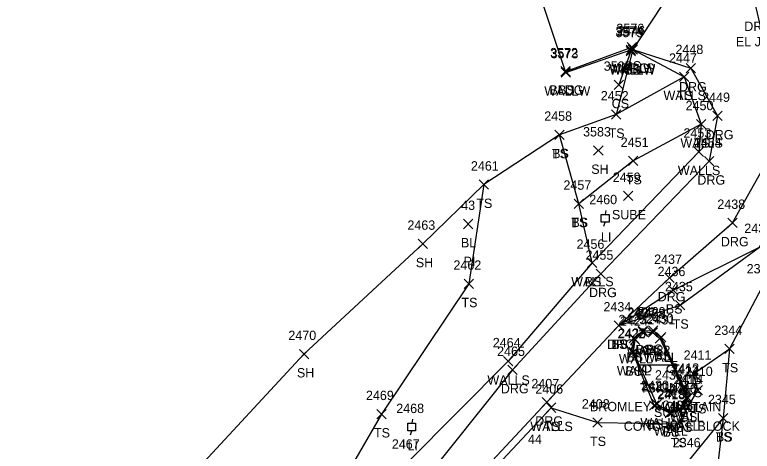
# Model space of a CAD drawing. Extents: x 49137 to 50946, y 9590 to 10709.
# Drawn here: x 49768.6 to 49926.3, y 10093.2 to 10186.5 of the extents above; entities that cross this region are included whole.
import ezdxf

# ---------------------------------------------------------------- set-up
doc = ezdxf.new("R2010")
doc.units = 0
for name, color, linetype in [('C_A', 7, 'Continuous'), ('C_C', 7, 'Continuous'), ('C_I', 7, 'Continuous'), ('C_TIC', 7, 'Continuous'), ('L_A', 7, 'Continuous'), ('L_C', 7, 'Continuous'), ('L_I', 7, 'Continuous'), ('L_TIC', 7, 'Continuous'), ('LBC', 7, 'Continuous'), ('LELB', 7, 'Continuous'), ('LSOGP', 7, 'Continuous'), ('LW', 7, 'Continuous'), ('LWS', 7, 'Continuous'), ('R_A', 7, 'Continuous'), ('R_I', 7, 'Continuous'), ('R_TIC', 7, 'Continuous'), ('RDG', 7, 'Continuous'), ('S_A', 7, 'Continuous'), ('S_C', 7, 'Continuous'), ('S_I', 7, 'Continuous'), ('SSGN', 7, 'Continuous'), ('U_A', 7, 'Continuous'), ('U_C', 7, 'Continuous'), ('U_I', 7, 'Continuous'), ('U_TIC', 7, 'Continuous'), ('ULP', 7, 'Continuous')]:
    doc.layers.add(name, color=color, linetype=linetype)

msp = doc.modelspace()

# ---------------------------------------------------------------- linework, layer by layer
at = {"layer": 'C_TIC'}
for points in [[(49864.54, 10140.8), (49866.54, 10142.8)], [(49866.54, 10140.8), (49864.54, 10142.8)]]:
    msp.add_lwpolyline(points, dxfattribs=at)
at = {"layer": 'L_TIC'}
for points in [[(49899.33, 10178.03), (49901.33, 10180.03)], [(49901.33, 10178.03), (49899.33, 10180.03)], [(49899.56, 10178.6), (49901.56, 10180.6)], [(49901.56, 10178.6), (49899.56, 10180.6)], [(49899.79, 10178.12), (49901.79, 10180.12)], [(49901.79, 10178.12), (49899.79, 10180.12)], [(49899.35, 10177.73), (49901.35, 10179.73)], [(49901.35, 10177.73), (49899.35, 10179.73)], [(49899.35, 10177.73), (49901.35, 10179.73)], [(49901.35, 10177.73), (49899.35, 10179.73)], [(49885.35, 10173.43), (49887.35, 10175.43)], [(49887.35, 10173.43), (49885.35, 10175.43)], [(49885.35, 10173.43), (49887.35, 10175.43)], [(49887.35, 10173.43), (49885.35, 10175.43)], [(49885.44, 10173.21), (49887.44, 10175.21)], [(49887.44, 10173.21), (49885.44, 10175.21)], [(49910.78, 10172.27), (49912.78, 10174.27)], [(49912.78, 10172.27), (49910.78, 10174.27)], [(49910.78, 10172.27), (49912.78, 10174.27)], [(49912.78, 10172.27), (49910.78, 10174.27)], [(49896.81, 10170.55), (49898.81, 10172.55)], [(49898.81, 10170.55), (49896.81, 10172.55)], [(49896.19, 10164.22), (49898.19, 10166.22)], [(49898.19, 10164.22), (49896.19, 10166.22)], [(49914.41, 10162.12), (49916.41, 10164.12)], [(49916.41, 10162.12), (49914.41, 10164.12)], [(49914.41, 10162.12), (49916.41, 10164.12)], [(49916.41, 10162.12), (49914.41, 10164.12)], [(49884.09, 10159.86), (49886.09, 10161.86)], [(49886.09, 10159.86), (49884.09, 10161.86)], [(49884.09, 10159.86), (49886.09, 10161.86)], [(49886.09, 10159.86), (49884.09, 10161.86)], [(49892.4, 10156.51), (49894.4, 10158.51)], [(49894.4, 10156.51), (49892.4, 10158.51)], [(49913.87, 10156.25), (49915.87, 10158.25)], [(49915.87, 10156.25), (49913.87, 10158.25)], [(49899.88, 10154.28), (49901.88, 10156.28)], [(49901.88, 10154.28), (49899.88, 10156.28)], [(49867.9, 10149.22), (49869.9, 10151.22)], [(49869.9, 10149.22), (49867.9, 10151.22)], [(49888.2, 10145.12), (49890.2, 10147.12)], [(49890.2, 10145.12), (49888.2, 10147.12)], [(49888.2, 10145.12), (49890.2, 10147.12)], [(49890.2, 10145.12), (49888.2, 10147.12)], [(49854.88, 10136.56), (49856.88, 10138.56)], [(49856.88, 10136.56), (49854.88, 10138.56)], [(49891.06, 10132.5), (49893.06, 10134.5)], [(49893.06, 10132.5), (49891.06, 10134.5)], [(49891.06, 10132.5), (49893.06, 10134.5)], [(49893.06, 10132.5), (49891.06, 10134.5)], [(49864.73, 10128.02), (49866.73, 10130.02)], [(49866.73, 10128.02), (49864.73, 10130.02)], [(49908.39, 10126.66), (49910.39, 10128.66)], [(49910.39, 10126.66), (49908.39, 10128.66)], [(49909.91, 10123.43), (49911.91, 10125.43)], [(49911.91, 10123.43), (49909.91, 10125.43)], [(49896.76, 10119.11), (49898.76, 10121.11)], [(49898.76, 10119.11), (49896.76, 10121.11)], [(49896.76, 10119.11), (49898.76, 10121.11)], [(49898.76, 10119.11), (49896.76, 10121.11)], [(49901.89, 10117.97), (49903.89, 10119.97)], [(49903.89, 10117.97), (49901.89, 10119.97)], [(49904.11, 10118.04), (49906.11, 10120.04)], [(49906.11, 10118.04), (49904.11, 10120.04)], [(49899.96, 10116.37), (49901.96, 10118.37)], [(49901.96, 10116.37), (49899.96, 10118.37)], [(49901.93, 10117.77), (49903.93, 10119.77)], [(49903.93, 10117.77), (49901.93, 10119.77)], [(49904.03, 10117.63), (49906.03, 10119.63)], [(49906.03, 10117.63), (49904.03, 10119.63)], [(49905.86, 10116.6), (49907.86, 10118.6)], [(49907.86, 10116.6), (49905.86, 10118.6)], [(49905.86, 10116.6), (49907.86, 10118.6)], [(49907.86, 10116.6), (49905.86, 10118.6)], [(49900.3, 10116.04), (49902.3, 10118.04)], [(49902.3, 10116.04), (49900.3, 10118.04)], [(49905.59, 10116.33), (49907.59, 10118.33)], [(49907.59, 10116.33), (49905.59, 10118.33)], [(49905.59, 10116.33), (49907.59, 10118.33)], [(49907.59, 10116.33), (49905.59, 10118.33)], [(49899.76, 10113.35), (49901.76, 10115.35)], [(49901.76, 10113.35), (49899.76, 10115.35)], [(49899.89, 10113.47), (49901.89, 10115.47)], [(49901.89, 10113.47), (49899.89, 10115.47)], [(49920.48, 10114.09), (49922.48, 10116.09)], [(49922.48, 10114.09), (49920.48, 10116.09)], [(49829.47, 10113), (49831.47, 10115)], [(49831.47, 10113), (49829.47, 10115)], [(49873.14, 10111.45), (49875.14, 10113.45)], [(49875.14, 10111.45), (49873.14, 10113.45)], [(49912.76, 10108.78), (49914.76, 10110.78)], [(49914.76, 10108.78), (49912.76, 10110.78)], [(49910.61, 10105.6), (49912.61, 10107.6)], [(49912.61, 10105.6), (49910.61, 10107.6)], [(49910.61, 10105.6), (49912.61, 10107.6)], [(49912.61, 10105.6), (49910.61, 10107.6)], [(49910.72, 10106.01), (49912.72, 10108.01)], [(49912.72, 10106.01), (49910.72, 10108.01)], [(49910.72, 10106.01), (49912.72, 10108.01)], [(49912.72, 10106.01), (49910.72, 10108.01)], [(49913.69, 10105.31), (49915.69, 10107.31)], [(49915.69, 10105.31), (49913.69, 10107.31)], [(49904.9, 10102.32), (49906.9, 10104.32)], [(49906.9, 10102.32), (49904.9, 10104.32)], [(49911.17, 10103.57), (49913.17, 10105.57)], [(49913.17, 10103.57), (49911.17, 10105.57)], [(49911.56, 10103.61), (49913.56, 10105.61)], [(49913.56, 10103.61), (49911.56, 10105.61)], [(49882.33, 10101.54), (49884.33, 10103.54)], [(49884.33, 10101.54), (49882.33, 10103.54)], [(49882.33, 10101.54), (49884.33, 10103.54)], [(49884.33, 10101.54), (49882.33, 10103.54)], [(49904.33, 10102), (49906.33, 10104)], [(49906.33, 10102), (49904.33, 10104)], [(49910.25, 10101.62), (49912.25, 10103.62)], [(49912.25, 10101.62), (49910.25, 10103.62)], [(49910.51, 10101.33), (49912.51, 10103.33)], [(49912.51, 10101.33), (49910.51, 10103.33)], [(49846.02, 10100.17), (49848.02, 10102.17)], [(49848.02, 10100.17), (49846.02, 10102.17)], [(49907.72, 10100.34), (49909.72, 10102.34)], [(49909.72, 10100.34), (49907.72, 10102.34)], [(49907.76, 10100.54), (49909.76, 10102.54)], [(49909.76, 10100.54), (49907.76, 10102.54)], [(49919.1, 10099.3), (49921.1, 10101.3)], [(49921.1, 10099.3), (49919.1, 10101.3)], [(49919.1, 10099.3), (49921.1, 10101.3)], [(49921.1, 10099.3), (49919.1, 10101.3)], [(49892.22, 10098.35), (49894.22, 10100.35)], [(49894.22, 10098.35), (49892.22, 10100.35)], [(49909.47, 10098.06), (49911.47, 10100.06)], [(49911.47, 10098.06), (49909.47, 10100.06)]]:
    msp.add_lwpolyline(points, dxfattribs=at)
at = {"layer": 'LBC'}
msp.add_lwpolyline([(49886.35, 10174.43), (49872.96, 10214.58), (49870.73, 10223.1), (49860.63, 10220.72)], dxfattribs=at)
at = {"layer": 'LELB'}
for points in [[(49955.98, 10224.66), (49962.11, 10206.73), (49963.32, 10197.72), (49964.68, 10176.23), (49967.05, 10162.1), (49944.13, 10145.25), (49928.38, 10128.24), (49921.48, 10115.09), (49920.1, 10100.3), (49918.19, 10083.85), (49918.93, 10078.25)], [(49897.76, 10120.11), (49909.39, 10127.66), (49927.87, 10136.88), (49941.26, 10158.78), (49931.78, 10188.79), (49933.01, 10213.1)], [(49886.35, 10174.43), (49900.56, 10179.6)], [(49900.35, 10178.73), (49897.81, 10171.55)], [(49911.78, 10173.27), (49897.19, 10165.22), (49885.09, 10160.86), (49868.9, 10150.22), (49865.73, 10129.02), (49847.02, 10101.17), (49823, 10059.67)], [(49915.41, 10163.12), (49900.88, 10155.28), (49889.2, 10146.12)], [(49892.06, 10133.5), (49889.2, 10146.12), (49885.09, 10160.86)], [(49897.76, 10120.11), (49910.91, 10124.43), (49927.87, 10136.88)], [(49911.72, 10107.01), (49912.56, 10104.61), (49911.51, 10102.33), (49908.72, 10101.34), (49905.33, 10103), (49900.76, 10114.35), (49900.96, 10117.37), (49902.89, 10118.97), (49905.11, 10119.04), (49906.86, 10117.6)], [(49911.72, 10107.01), (49906.86, 10117.6)], [(49913.76, 10109.78), (49921.48, 10115.09)], [(49883.33, 10102.54), (49893.22, 10099.35), (49910.47, 10099.06), (49914.69, 10106.31), (49913.76, 10109.78)], [(49920.1, 10100.3), (49912.63, 10091.09), (49904.43, 10086.39)]]:
    msp.add_lwpolyline(points, dxfattribs=at)
at = {"layer": 'LSOGP'}
msp.add_lwpolyline([(49921.15, 10210.06), (49900.78, 10179.13), (49897.19, 10165.22), (49885.09, 10160.86), (49868.89, 10150.22), (49855.88, 10137.57), (49830.46, 10114), (49806.41, 10088.03), (49776.2, 10083.52), (49760.59, 10076.2)], dxfattribs=at)
at = {"layer": 'LW'}
for points in [[(49886.44, 10174.21), (49900.33, 10179.03), (49900.35, 10178.73)], [(49911.61, 10106.6), (49912.17, 10104.57), (49911.25, 10102.62), (49908.76, 10101.54), (49905.9, 10103.32), (49900.89, 10114.47), (49901.3, 10117.04), (49902.93, 10118.77), (49905.03, 10118.63), (49906.59, 10117.33)], [(49911.61, 10106.6), (49906.59, 10117.33)]]:
    msp.add_lwpolyline(points, dxfattribs=at)
at = {"layer": 'LWS'}
for points in [[(49900.79, 10179.12), (49911.78, 10173.27), (49915.41, 10163.12), (49914.87, 10157.25), (49892.06, 10133.5), (49874.14, 10112.45), (49852.55, 10090.77), (49823, 10059.67), (49804.33, 10038.47)], [(49828.96, 10027.58), (49828.08, 10031.4), (49832.44, 10045.24), (49853.25, 10070.35), (49883.33, 10102.54)]]:
    msp.add_lwpolyline(points, dxfattribs=at)
at = {"layer": 'R_TIC'}
for points in [[(49899.79, 10178.12), (49901.79, 10180.12)], [(49901.79, 10178.12), (49899.79, 10180.12)], [(49912.16, 10174.13), (49914.16, 10176.13)], [(49914.16, 10174.13), (49912.16, 10176.13)], [(49917.87, 10163.89), (49919.87, 10165.89)], [(49919.87, 10163.89), (49917.87, 10165.89)], [(49916.09, 10154.21), (49918.09, 10156.21)], [(49918.09, 10154.21), (49916.09, 10156.21)], [(49921.11, 10141.03), (49923.11, 10143.03)], [(49923.11, 10141.03), (49921.11, 10143.03)], [(49892.92, 10130.16), (49894.92, 10132.16)], [(49894.92, 10130.16), (49892.92, 10132.16)], [(49907.6, 10129.27), (49909.6, 10131.27)], [(49909.6, 10129.27), (49907.6, 10131.27)], [(49896.76, 10119.11), (49898.76, 10121.11)], [(49898.76, 10119.11), (49896.76, 10121.11)], [(49874.07, 10109.6), (49876.07, 10111.6)], [(49876.07, 10109.6), (49874.07, 10111.6)], [(49881.42, 10102.69), (49883.42, 10104.69)], [(49883.42, 10102.69), (49881.42, 10104.69)]]:
    msp.add_lwpolyline(points, dxfattribs=at)
at = {"layer": 'RDG'}
for points in [[(49797.89, 10003.45), (49806.67, 10020.9), (49821.46, 10037.44), (49832.34, 10049.67), (49852.34, 10071.47), (49882.42, 10103.69), (49897.76, 10120.11), (49908.6, 10130.27), (49922.11, 10142.03), (49933.26, 10161.9), (49927.13, 10188.06), (49921.15, 10210.06)], [(49900.79, 10179.12), (49913.16, 10175.13), (49918.87, 10164.89), (49917.09, 10155.21), (49893.92, 10131.16), (49875.07, 10110.6), (49855.27, 10085.88), (49826.17, 10056.49), (49807.26, 10034.98), (49792.19, 10024.42), (49776.73, 10026.67)]]:
    msp.add_lwpolyline(points, dxfattribs=at)
at = {"layer": 'SSGN'}
for p, q in [((49902.1, 10111.7), (49910.7, 10111.7)), ((49906.13, 10110.8), (49906.13, 10110.8))]:
    msp.add_line(p, q, dxfattribs=at)
for centre in [(49903.76, 10110.87), (49908.98, 10110.8)]:
    msp.add_circle(centre, 0.833, dxfattribs=at)
at = {"layer": 'U_TIC'}
for points in [[(49898.77, 10146.8), (49900.77, 10148.8)], [(49900.77, 10146.8), (49898.77, 10148.8)], [(49907.77, 10104.54), (49909.77, 10106.54)], [(49909.77, 10104.54), (49907.77, 10106.54)]]:
    msp.add_lwpolyline(points, dxfattribs=at)
at = {"layer": 'ULP'}
for p, q in [((49894.03, 10142.19), (49894.03, 10143.86)), ((49894.03, 10143.86), (49895.69, 10143.86)), ((49895.03, 10144.69), (49894.86, 10143.86)), ((49895.69, 10143.86), (49895.69, 10142.19)), ((49895.69, 10142.19), (49894.03, 10142.19)), ((49894.61, 10141.36), (49894.86, 10142.19)), ((49894.86, 10143.03), (49894.86, 10143.03)), ((49853.67, 10100.06), (49853.5, 10099.23)), ((49852.67, 10097.56), (49852.67, 10099.23)), ((49852.67, 10099.23), (49854.33, 10099.23)), ((49853.5, 10098.39), (49853.5, 10098.39)), ((49854.33, 10099.23), (49854.33, 10097.56)), ((49854.33, 10097.56), (49852.67, 10097.56)), ((49853.25, 10096.73), (49853.5, 10097.56))]:
    msp.add_line(p, q, dxfattribs=at)

# ---------------------------------------------------------------- texts
at = {"layer": 'C_A'}
msp.add_text('BL', height=2, dxfattribs=at).set_placement((49864.02, 10136.8))
at = {"layer": 'C_C'}
msp.add_text('PI', height=2, dxfattribs=at).set_placement((49864.59, 10132.8))
at = {"layer": 'C_I'}
for s, p in [('43', (49864.07, 10144.8)), ('44', (49878.35, 10094.8))]:
    msp.add_text(s, height=2, dxfattribs=at).set_placement(p)
at = {"layer": 'L_A'}
for s, p in [('WALLW', (49895.75, 10174.03)), ('WALLW', (49895.76, 10173.73)), ('WALLS', (49896.33, 10174.12)), ('CS', (49898.79, 10173.73)), ('BS', (49899, 10174.6)), ('WALLW', (49881.86, 10169.21)), ('BLDG', (49882.94, 10169.43)), ('BS', (49884.79, 10169.43)), ('WALLS', (49907.33, 10168.27)), ('TS', (49910.19, 10168.27)), ('CS', (49896.25, 10166.55)), ('TS', (49895.6, 10160.22)), ('WALLS', (49910.96, 10158.12)), ('TS', (49913.82, 10158.12)), ('TS', (49883.5, 10155.86)), ('BS', (49883.53, 10155.86)), ('SH', (49891.89, 10152.51)), ('WALLS', (49910.41, 10152.25)), ('TS', (49899.29, 10150.28)), ('TS', (49867.31, 10145.22)), ('TS', (49887.61, 10141.12)), ('BS', (49887.64, 10141.12)), ('SH', (49854.37, 10132.56)), ('WALLS', (49887.6, 10128.5)), ('BS', (49890.5, 10128.5)), ('TS', (49864.13, 10124.02)), ('BS', (49907.83, 10122.66)), ('TS', (49909.31, 10119.43)), ('TS', (49896.17, 10115.11)), ('BS', (49896.2, 10115.11)), ('WALL', (49899.42, 10113.77)), ('WALL', (49901.51, 10113.63)), ('BS', (49901.33, 10113.97)), ('BS', (49903.55, 10114.04)), ('WALL', (49897.79, 10112.04)), ('BS', (49899.4, 10112.37)), ('WALL', (49903.08, 10112.33)), ('WALL', (49903.08, 10112.33)), ('BS', (49905.31, 10112.6)), ('BS', (49905.31, 10112.6)), ('TS', (49919.89, 10110.09)), ('SH', (49828.95, 10109)), ('WALL', (49897.37, 10109.47)), ('BS', (49899.2, 10109.35)), ('WALLS', (49869.68, 10107.45)), ('TS', (49912.17, 10104.78)), ('WALL', (49908.1, 10101.6)), ('WALL', (49908.1, 10101.6)), ('BS', (49910.16, 10102.01)), ('BS', (49910.16, 10102.01)), ('TS', (49913.1, 10101.31)), ('WALL', (49908.66, 10099.57)), ('BS', (49911, 10099.61)), ('WALLS', (49878.87, 10097.54)), ('TS', (49881.74, 10097.54)), ('WALL', (49902.39, 10098.32)), ('BS', (49903.77, 10098)), ('WALL', (49907.74, 10097.62)), ('TS', (49845.43, 10096.17)), ('WALL', (49905.25, 10096.54)), ('BS', (49907.16, 10096.34)), ('BS', (49909.95, 10097.33)), ('TS', (49891.63, 10094.35)), ('TS', (49918.51, 10095.3)), ('BS', (49918.54, 10095.3)), ('TS', (49908.88, 10094.06))]:
    msp.add_text(s, height=2, dxfattribs=at).set_placement(p)
at = {"layer": 'L_C'}
msp.add_text('CONCRETE BLOCK', height=2, dxfattribs=at).set_placement((49898.85, 10097.6))
msp.add_text('CONCRETE BLOCK', height=2, dxfattribs=at).set_placement((49898.85, 10097.6))
at = {"layer": 'L_I'}
for s, p in [('3576', (49897.25, 10182.6)), ('3574', (49897.07, 10182.03)), ('3575', (49897.09, 10181.73)), ('3575', (49897.09, 10181.73)), ('2446', (49897.47, 10182.12)), ('3572', (49883.09, 10177.43)), ('3572', (49883.09, 10177.43)), ('3573', (49883.18, 10177.21)), ('2447', (49908.52, 10176.27)), ('2447', (49908.52, 10176.27)), ('3582', (49894.55, 10174.55)), ('2452', (49893.93, 10168.22)), ('2450', (49912.07, 10166.12)), ('2450', (49912.07, 10166.12)), ('2458', (49881.83, 10163.86)), ('2458', (49881.83, 10163.86)), ('3583', (49890.14, 10160.51)), ('2453', (49911.61, 10160.25)), ('2451', (49898.19, 10158.28)), ('2461', (49866.16, 10153.22)), ('2457', (49885.94, 10149.12)), ('2457', (49885.94, 10149.12)), ('2463', (49852.57, 10140.56)), ('2439', (49924.61, 10139.88)), ('2439', (49924.61, 10139.88)), ('2456', (49888.74, 10136.5)), ('2456', (49888.74, 10136.5)), ('2462', (49862.42, 10132.02)), ('2436', (49906.07, 10130.66)), ('2343', (49925.12, 10131.24)), ('2435', (49907.65, 10127.43)), ('2434', (49894.5, 10123.11)), ('2434', (49894.5, 10123.11)), ('2426', (49899.57, 10121.97)), ('2427', (49899.68, 10121.77)), ('2428', (49901.77, 10121.63)), ('2429', (49901.84, 10122.04)), ('2425', (49897.7, 10120.37)), ('2424', (49898.04, 10120.04)), ('2430', (49903.52, 10120.6)), ('2430', (49903.52, 10120.6)), ('2431', (49903.9, 10120.33)), ('2431', (49903.9, 10120.33)), ('2344', (49918.22, 10118.09)), ('2470', (49827.12, 10117)), ('2422', (49897.5, 10117.35)), ('2423', (49897.63, 10117.47)), ('2464', (49870.83, 10115.45)), ('2411', (49911.64, 10112.78)), ('2413', (49909.02, 10110.01)), ('2413', (49909.02, 10110.01)), ('2412', (49908.92, 10109.6)), ('2412', (49908.92, 10109.6)), ('2410', (49911.91, 10109.31)), ('2415', (49909.48, 10107.57)), ('2414', (49909.87, 10107.61)), ('2406', (49879.93, 10105.54)), ('2406', (49879.93, 10105.54)), ('2420', (49902.55, 10106.32)), ('2421', (49902.63, 10106)), ('2416', (49908.51, 10105.62)), ('2417', (49908.81, 10105.33)), ('2469', (49843.71, 10104.17)), ('2418', (49906.02, 10104.34)), ('2419', (49906.06, 10104.54)), ('2408', (49889.88, 10102.35)), ('2345', (49916.84, 10103.3)), ('2345', (49916.84, 10103.3)), ('2409', (49907.13, 10102.06)), ('2467', (49849.25, 10093.77)), ('2346', (49909.32, 10094.09))]:
    msp.add_text(s, height=2, dxfattribs=at).set_placement(p)
at = {"layer": 'R_A'}
for p in [(49924.61, 10183.06), (49898.27, 10174.12), (49910.65, 10170.13), (49916.36, 10159.89), (49914.58, 10150.21), (49919.6, 10137.03), (49891.41, 10126.16), (49906.09, 10125.27), (49895.25, 10115.11), (49872.55, 10105.6), (49879.91, 10098.69)]:
    msp.add_text('DRG', height=2, dxfattribs=at).set_placement(p)
at = {"layer": 'R_I'}
for s, p in [('2446', (49897.47, 10182.12)), ('2448', (49909.9, 10178.13)), ('2449', (49915.6, 10167.89)), ('2454', (49913.83, 10158.21)), ('2438', (49918.85, 10145.03)), ('2455', (49890.66, 10134.16)), ('2437', (49905.34, 10133.27)), ('2434', (49894.5, 10123.11)), ('2465', (49871.76, 10113.6)), ('2407', (49879.08, 10106.69))]:
    msp.add_text(s, height=2, dxfattribs=at).set_placement(p)
at = {"layer": 'S_A'}
msp.add_text('TSIGN', height=2, dxfattribs=at).set_placement((49902.3, 10105.78))
at = {"layer": 'S_C'}
msp.add_text('BROMLEY MOUNTAIN', height=2, dxfattribs=at).set_placement((49891.61, 10101.78))
at = {"layer": 'S_I'}
msp.add_text('2432', height=2, dxfattribs=at).set_placement((49902.86, 10113.78))
at = {"layer": 'U_A'}
for s, p in [('SUBE', (49896.31, 10142.8)), ('LI', (49893.96, 10138.03)), ('SUBE', (49905.3, 10100.54)), ('LI', (49852.6, 10093.39))]:
    msp.add_text(s, height=2, dxfattribs=at).set_placement(p)
at = {"layer": 'U_C'}
msp.add_text('EL JCT BOX', height=2, dxfattribs=at).set_placement((49922.82, 10179.79))
at = {"layer": 'U_I'}
for s, p in [('2459', (49896.5, 10150.8)), ('2460', (49891.47, 10146.03)), ('2433', (49905.51, 10108.54)), ('2468', (49850.19, 10101.39))]:
    msp.add_text(s, height=2, dxfattribs=at).set_placement(p)

doc.saveas('drawing.dxf')
